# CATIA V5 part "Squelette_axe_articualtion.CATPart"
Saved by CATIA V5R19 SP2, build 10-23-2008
Part number: squelette_axe_articulation
Bounding box of the stored display mesh (mm): x -23 to 55, y -294 to -294, z -144 to -144
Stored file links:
  C:\Users\Pauline\Desktop\CFAO_Catia\Compte_rendu\pmayet_assemblage_animation4\Squelette_axe_articualtion.CATPart
  C:\Users\Pauline\Desktop\CFAO_Catia\Compte_rendu\pmayet_assemblage_animation4\pmayet_assemblage_animation.CATProduct
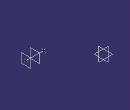
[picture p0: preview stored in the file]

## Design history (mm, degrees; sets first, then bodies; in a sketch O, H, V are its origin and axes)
Set1
  Point1: linked copy from another document
  Point2 "Point.15_biellete_a": linked copy from another document
Set2
  Line1: type PtPt, FirstPoint Point1, SecondPoint Point2
  Plane1: type Normal, Curve Line1
  Plane2: type Normal, Curve Line1, RefPoint Point1
Body1 (main body)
